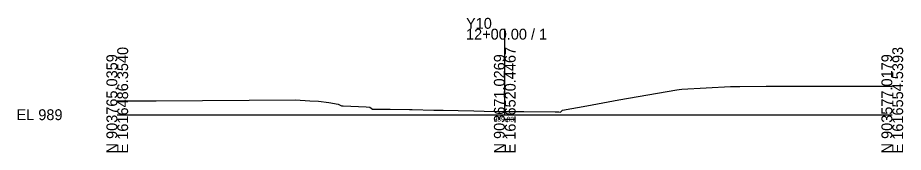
# Model space of a CAD drawing. Extents: x -26 to 203, y -10 to 3046.
# Drawn here: x -25.7 to 202.8, y 1990.3 to 2025 of the extents above; entities that cross this region are included whole.
import ezdxf

# ---------------------------------------------------------------- set-up
doc = ezdxf.new("R2010")
doc.units = 0
for name, color, linetype in [('Exist Cross Section Cell', 7, 'Continuous'), ('Exist XS Center Line Elevation Label', 7, 'Continuous'), ('Exist XS Ground Line', 7, 'Continuous')]:
    doc.layers.add(name, color=color, linetype=linetype)

msp = doc.modelspace()

# ---------------------------------------------------------------- linework, layer by layer
at = {"layer": 'Exist Cross Section Cell'}
for p, q in [((100, 2000), (100, 2022.17)), ((0, 2000), (100, 2000)), ((100, 2000), (200, 2000))]:
    msp.add_line(p, q, dxfattribs=at)
at = {"layer": 'Exist XS Ground Line'}
for p, q in [((144.37, 2006.43), (144.97, 2006.54)), ((144.97, 2006.54), (145.73, 2006.58)), ((145.73, 2006.58), (158.28, 2007.24)), ((158.28, 2007.24), (160.69, 2007.27)), ((160.69, 2007.27), (167.44, 2007.32)), ((167.44, 2007.32), (178.73, 2007.39)), ((178.73, 2007.39), (179.99, 2007.37)), ((179.99, 2007.37), (183.34, 2007.34)), ((183.34, 2007.34), (184.6, 2007.32)), ((184.6, 2007.32), (186.15, 2007.33)), ((186.15, 2007.33), (187.82, 2007.36)), ((187.82, 2007.36), (190.75, 2007.33)), ((190.75, 2007.33), (192.61, 2007.34)), ((192.61, 2007.34), (193.11, 2007.34)), ((193.11, 2007.34), (195.36, 2007.33)), ((195.36, 2007.33), (200, 2007.32)), ((129.47, 2003.82), (144.37, 2006.43)), ((0, 2003.62), (10.07, 2003.62)), ((10.07, 2003.62), (45.98, 2003.83)), ((45.98, 2003.83), (49.72, 2003.59)), ((49.72, 2003.59), (51.93, 2003.45)), ((51.93, 2003.45), (54.61, 2003.11)), ((54.61, 2003.11), (57.02, 2002.7)), ((57.02, 2002.7), (57.89, 2002.29)), ((57.89, 2002.29), (58.32, 2002.27)), ((58.32, 2002.27), (64.25, 2001.99)), ((64.25, 2001.99), (65.2, 2001.97)), ((65.2, 2001.97), (65.88, 2001.45)), ((114.91, 2001.17), (121.2, 2002.33)), ((121.2, 2002.33), (129.47, 2003.82)), ((65.88, 2001.45), (67.18, 2001.45)), ((67.18, 2001.45), (70.41, 2001.4)), ((70.41, 2001.4), (75.43, 2001.35)), ((75.43, 2001.35), (76.09, 2001.35)), ((76.09, 2001.35), (81.66, 2001.2)), ((81.66, 2001.2), (84.12, 2001.19)), ((84.12, 2001.19), (87.93, 2001.11)), ((87.93, 2001.11), (92.04, 2001.03)), ((92.04, 2001.03), (94.65, 2000.95)), ((94.65, 2000.95), (100.08, 2000.83)), ((100.08, 2000.83), (104.89, 2000.79)), ((104.89, 2000.79), (113.01, 2000.73)), ((113.01, 2000.73), (113.99, 2000.71)), ((113.99, 2000.71), (114.41, 2000.69)), ((114.41, 2000.69), (114.91, 2001.17))]:
    msp.add_line(p, q, dxfattribs=at)

# ---------------------------------------------------------------- texts
at = {"layer": 'Exist Cross Section Cell'}
for s, p in [('Y10', (90, 2022.17)), ('12+00.00 / 1', (90, 2019.37)), ('EL 989', (-26, 1998.6))]:
    msp.add_text(s, height=2.8, dxfattribs=at).set_placement(p)
for s, p in [('E 1616486.3540', (2.8, 1990)), ('E 1616520.4467', (102.8, 1990)), ('E 1616554.5393', (202.8, 1990)), ('N 903765.0359', (0, 1990)), ('N 903671.0269', (100, 1990)), ('N 903577.0179', (200, 1990))]:
    msp.add_text(s, height=2.8, rotation=90, dxfattribs=at).set_placement(p)
at = {"layer": 'Exist XS Center Line Elevation Label'}
msp.add_text('989.83', height=1.25, dxfattribs=at).set_placement((97.1, 1998.2))

doc.saveas('drawing.dxf')
